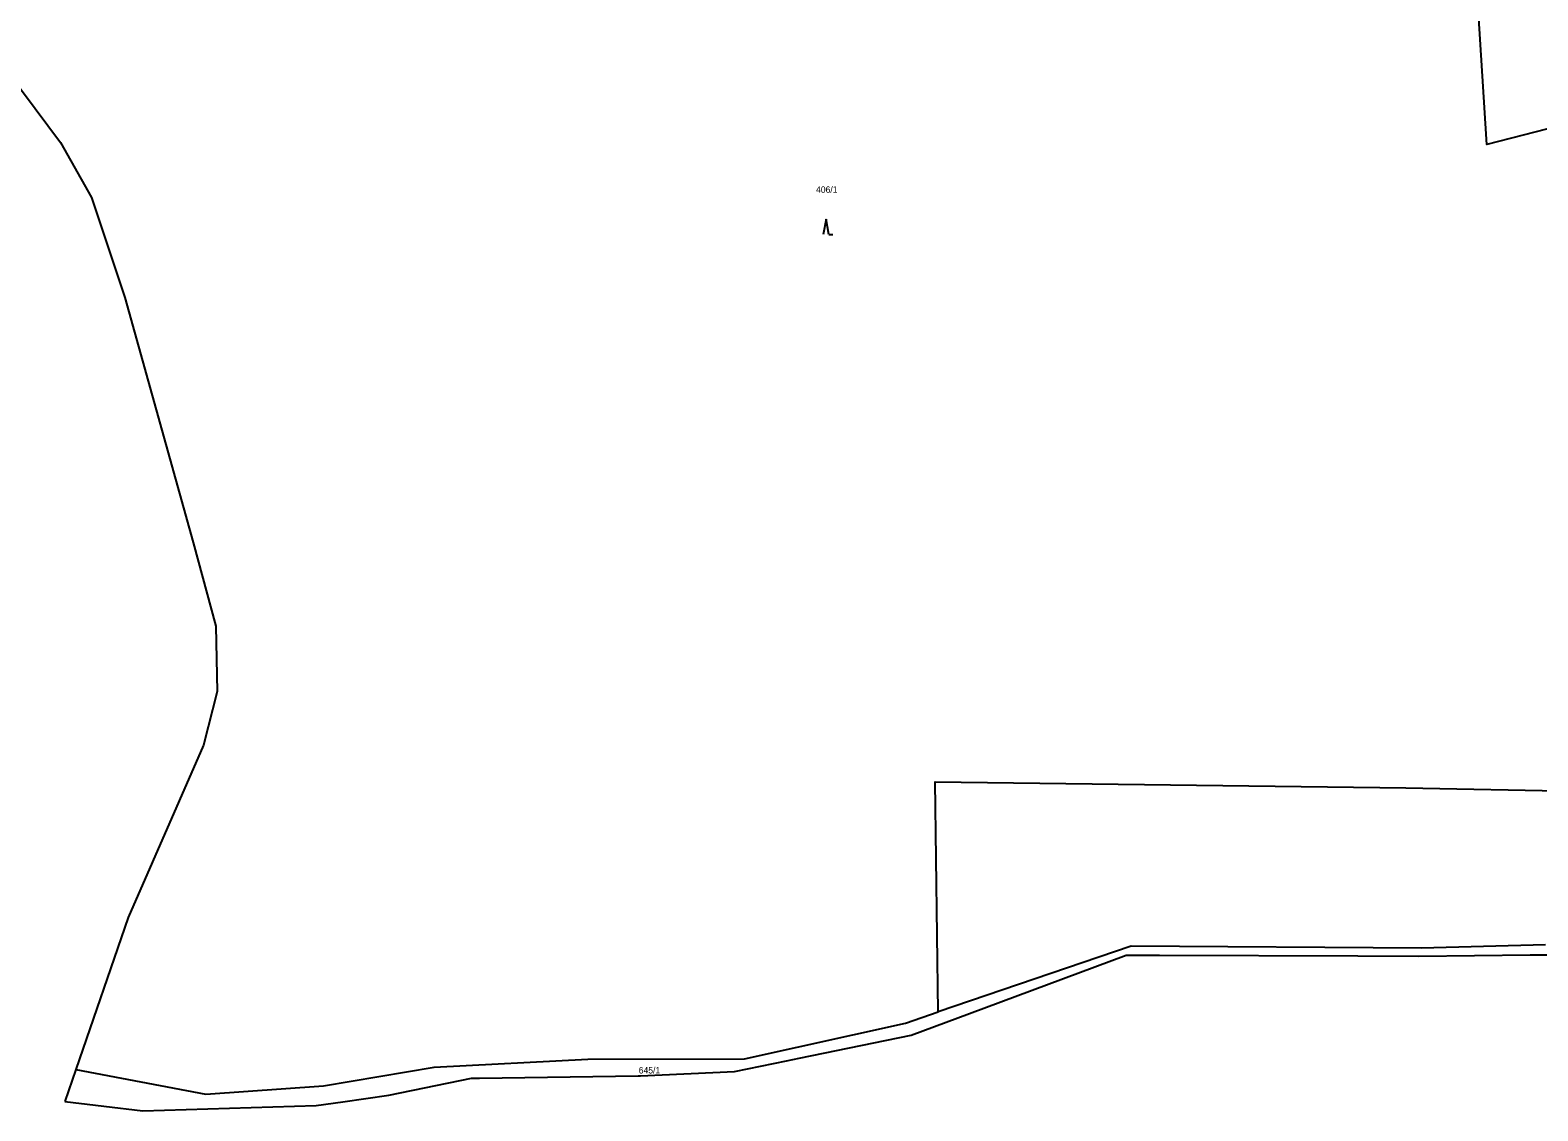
# Model space of a CAD drawing. Extents: x -746176 to -739709, y -1128407 to -1124482.
# Drawn here: x -744472.8 to -744073.3, y -1127584.5 to -1127298.3 of the extents above; entities that cross this region are included whole.
import ezdxf

# ---------------------------------------------------------------- set-up
doc = ezdxf.new("R2010")
doc.units = 0
for name, color, linetype in [('Vrstva 33', 7, 'Continuous'), ('Vrstva 42', 7, 'Continuous'), ('Vrstva 44', 7, 'Continuous')]:
    doc.layers.add(name, color=color, linetype=linetype)

msp = doc.modelspace()

# ---------------------------------------------------------------- linework, layer by layer
at = {"layer": 'Vrstva 33'}
for p, q in [((-744485.52, -1127300.23), (-744464.77, -1127328.01)), ((-744464.77, -1127328.01), (-744456.52, -1127342.64)), ((-744223.95, -1127558.72), (-744182.46, -1127543.26)), ((-744182.46, -1127543.26), (-744173.58, -1127543.29)), ((-744173.58, -1127543.29), (-744121.06, -1127543.47)), ((-744121.06, -1127543.47), (-744104.89, -1127543.52)), ((-744104.89, -1127543.52), (-744075.38, -1127543.22)), ((-744075.38, -1127543.22), (-744069.49, -1127543.16)), ((-744239.37, -1127564.46), (-744223.95, -1127558.72)), ((-744269.08, -1127570.59), (-744239.37, -1127564.46)), ((-744460.69, -1127573.57), (-744463.62, -1127582.08)), ((-744272.39, -1127571.27), (-744269.08, -1127570.59)), ((-744353.71, -1127575.84), (-744311.75, -1127575.29)), ((-744311.75, -1127575.29), (-744311.09, -1127575.26)), ((-744463.62, -1127582.08), (-744442.97, -1127584.52)), ((-744397, -1127583.1), (-744389.95, -1127582.1)), ((-744442.97, -1127584.52), (-744397, -1127583.1))]:
    msp.add_line(p, q, dxfattribs=at)
for points in [[(-744232.26, -1127558.32), (-744232.99, -1127497.42), (-744108.28, -1127499), (-744063.15, -1127499.85), (-744059.18, -1127436.28), (-744054.92, -1127320.35), (-744086.9, -1127328.53), (-744091.8, -1127250.55), (-744074.74, -1127255.35), (-744063.54, -1127264.6), (-744064.61, -1127288.79), (-744055.9, -1127290.74), (-744054.3, -1127303.37), (-744044.5, -1127305.2)], [(-744456.52, -1127342.64), (-744447.69, -1127369.09), (-744429.62, -1127433.96)], [(-744429.62, -1127433.96), (-744423.64, -1127456.16), (-744423.24, -1127473.47), (-744426.9, -1127487.71)], [(-744426.9, -1127487.71), (-744446.84, -1127533.33), (-744460.69, -1127573.57)], [(-744071.31, -1127540.54), (-744104.13, -1127541.44), (-744181.13, -1127540.94), (-744232.26, -1127558.32)], [(-744460.69, -1127573.57), (-744426.24, -1127580.1), (-744395.07, -1127577.86), (-744365.75, -1127572.94), (-744325.02, -1127570.79), (-744283.5, -1127570.77), (-744240.92, -1127561.26), (-744232.26, -1127558.32)], [(-744311.09, -1127575.26), (-744286.2, -1127574.12), (-744272.39, -1127571.27)], [(-744389.95, -1127582.1), (-744377.76, -1127580.37), (-744355.83, -1127575.87), (-744353.71, -1127575.84)]]:
    msp.add_lwpolyline(points, dxfattribs=at)
at = {"layer": 'Vrstva 44'}
for p, q in [((-744261.92, -1127348.37), (-744262.67, -1127352.37)), ((-744261.17, -1127352.37), (-744261.92, -1127348.37)), ((-744261.17, -1127352.37), (-744260.17, -1127352.37))]:
    msp.add_line(p, q, dxfattribs=at)

# ---------------------------------------------------------------- texts
at = {"layer": 'Vrstva 42'}
for s, p in [('406/1', (-744264.58, -1127341.36)), ('645/1', (-744311.56, -1127574.63))]:
    msp.add_text(s, height=1.7, dxfattribs=at).set_placement(p)

doc.saveas('drawing.dxf')
